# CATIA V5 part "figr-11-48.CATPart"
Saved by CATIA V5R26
Part number: Part1
Bounding box of the stored display mesh (mm): x -270.607 to 0, y -223.278 to 0, z -13.562 to 46.691
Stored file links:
  D:\_Deepak\CATIA\CATIA V5-6R2016_Deepak\Resources\Part files\Partfiles\c11_catia_v5_6r2016_prt\figr-11-48.CATPart
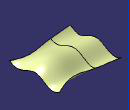
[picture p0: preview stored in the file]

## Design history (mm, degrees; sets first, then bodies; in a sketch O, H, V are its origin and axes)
Set1
  Sweep1: type Unspec, Profile Sketch2, Guide Sketch1
  Extrapol1: ToExtrapol edge of Sweep1, Support Sweep1, Length 100
Body1 (main body)
  Sketch1 on yz-plane, origin (0, 0, 0), H (0, 1, 0), V (0, 0, 1)
    spline S1 through (0, 0) (-40, -10) (-100, 20) (-170, 0) (-220, 10)
    point P1 (0, 0)
    coincidence: P1 O
  Sketch2 on zx-plane, origin (0, 0, 0), H (-1, 0, 0), V (0, 0, 1)
    spline S1 through (0, 0) (60, 30) (121.1814, 19.9844) (171.1814, 9.9844)
    point P1 (0, 0)
    coincidence: P1 O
